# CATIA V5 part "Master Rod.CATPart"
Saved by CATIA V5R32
Part number: Master Rod
Bounding box of the stored display mesh (mm): x -55.99 to 55.99, y -51.999 to 267.322, z -35 to 35
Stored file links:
  D:\PROJECTS\Project 2022\CATIA V5 6R 2022\Resources\Part Files\c12_catia_v5_6r2022_prt\c12_catia_v5-6r2022 figr_12-26\Master Rod.CATPart
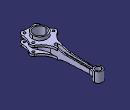
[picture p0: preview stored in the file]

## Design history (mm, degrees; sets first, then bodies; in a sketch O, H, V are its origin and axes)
Body1 (main body)
  Sketch1 on xy-plane, origin (0, 0, 0), H (1, 0, 0), V (0, 1, 0)
    arc A1 centre (0, 0) radius 31.5 from (-26.3425, 17.272) to (26.3425, 17.272) ccw
    arc A2 centre (0, 250) radius 17.5 from (14.7398, 240.5666) to (-14.7398, 240.5666) ccw
    point P1 (0, 250)
    line L1 (9, 220) -> (13, 60)
    point P2 (9, 220)
    point P3 (13, 60)
    arc A3 centre (94.6219, 62.0405) radius 81.6474 from (13, 60) to (26.3425, 17.272) ccw
    point P5 (26.3425, 17.272)
    arc A4 centre (45.4514, 220.9113) radius 36.4628 from (9, 220) to (14.7398, 240.5666) cw
    point P7 (14.7398, 240.5666)
    point P8 (-14.7398, 240.5666)
    point P9 (-9, 220)
    arc A5 centre (-45.4514, 220.9113) radius 36.4628 from (-9, 220) to (-14.7398, 240.5666) ccw
    point P11 (-13, 60)
    line L2 (-9, 220) -> (-13, 60)
    point P12 (-26.3425, 17.272)
    arc A6 centre (-94.6219, 62.0405) radius 81.6474 from (-13, 60) to (-26.3425, 17.272) cw
    radius A1 = 31.5
    radius A2 = 17.5
    distance P1 H = 250
    distance V P3 = 13
    distance P2 V = 9
    distance P1 P2 V = 30
    distance P3 P2 V = 160
    coincidence: P1 V
    tangency: A3 L1, A3 A1, A4 L1, A4 A2
    symmetry: P7 P8 V, P2 P9 V, A4 A5 V, P3 P11 V, L1 L2 V, P5 P12 V, A3 A6 V
  Pad1: profile Sketch1, direction (0, 0, 1), length 21, mirrored extent
  Sketch2 on face of Pad1, origin (0, 0, 21), H (1, 0, 0), V (0, 1, 0)
    point P1 (43, 16)
    point P2 (26, -39)
    arc A1 centre (43, 16) radius 13 from (53.3864, 8.1819) to (49.3111, 27.3653) ccw
    arc A2 centre (26, -39) radius 13 from (22.0235, -51.3769) to (38.9864, -38.4063) ccw
    reference projected line E1 (9, 220) -> (12.2872, 88.5122) from edge of Pad1
    arc A3 centre (84.2647, 90.3117) radius 72 from (49.3111, 27.3653) to (12.2872, 88.5122) cw
    point P5 (49.3111, 27.3653)
    point P6 (12.2872, 88.5122)
    arc A4 centre (110.9113, -35.118) radius 72 from (38.9864, -38.4063) to (53.3864, 8.1819) cw
    point P8 (38.9864, -38.4063)
    point P9 (53.3864, 8.1819)
    point P10 (-12.2872, 88.5122)
    point P11 (-49.3111, 27.3653)
    arc A5 centre (-84.2647, 90.3117) radius 72 from (-49.3111, 27.3653) to (-12.2872, 88.5122) ccw
    point P13 (-53.3864, 8.1819)
    arc A6 centre (-43, 16) radius 13 from (-53.3864, 8.1819) to (-49.3111, 27.3653) cw
    point P15 (-38.9864, -38.4063)
    arc A7 centre (-110.9113, -35.118) radius 72 from (-38.9864, -38.4063) to (-53.3864, 8.1819) ccw
    arc A8 centre (-26, -39) radius 13 from (-22.0235, -51.3769) to (-38.9864, -38.4063) cw
    line L1 (12.2872, 88.5122) -> (-12.2872, 88.5122)
    arc A9 centre (0, -119.9259) radius 72 from (-22.0235, -51.3769) to (22.0235, -51.3769) cw
    distance V P2 = 26
    distance P2 P1 H = 17
    distance P1 P2 V = 55
    distance P2 H = 39
    radius A1 = 13
    radius A2 = 13
    radius A3 = 72
    radius A4 = 72
    radius A9 = 72
    tangency: A3 E1, A3 A1, A4 A1, A4 A2, A9 A8, A9 A2
    symmetry: P6 P10 V, P5 P11 V, A3 A5 V, P9 P13 V, A1 A6 V, P8 P15 V, A4 A7 V, A2 A8 V
    horizontal: L1 H
  Pad2: profile Sketch2, direction (0, 0, -1), length 9
  Mirror1: of Pad2, Sketch2, about xy-plane
  Sketch3 on xy-plane, origin (0, 0, 0), H (1, 0, 0), V (0, 1, 0)
    circle A1 centre (0, 0) radius 31.5
    reference projected arc E1 centre (0, 0) radius 31.5 from (-26.3425, 17.272) to (26.3425, 17.272) ccw from edge of Pad2
    tangency: A1 E1
  Pad3: profile Sketch3, direction (0, 0, 1), length 35, mirrored extent
  Sketch4 on xy-plane, origin (0, 0, 0), H (1, 0, 0), V (0, 1, 0)
    circle A1 centre (0, 0) radius 26
    circle A2 centre (43, 16) radius 5
    circle A3 centre (26, -39) radius 5
    reference projected arc E1 centre (43, 16) radius 13 from (53.3864, 8.1819) to (49.3111, 27.3653) ccw from edge of Pad2
    reference projected arc E2 centre (26, -39) radius 13 from (22.0235, -51.3769) to (38.9864, -38.4063) ccw from edge of Pad2
    circle A4 centre (-26, -39) radius 5
    circle A5 centre (-43, 16) radius 5
    radius A1 = 26
    radius A3 = 5
    radius A2 = 5
    concentricity: A2 E1, A3 E2
    symmetry: A3 A4 V, A2 A5 V
  Pocket1: profile Sketch4, direction (0, 0, -1), length 35, mirrored extent
  Sketch5 on yz-plane, origin (0, 0, 0), H (0, 1, 0), V (0, 0, 1)
    line L1 (123.0834, 12) -> (250, 9)
    point P1 (123.0834, 12)
    point P2 (250, 9)
    arc A1 centre (124.9266, 89.9782) radius 78 from (88.5122, 21) to (123.0834, 12) ccw
    line L2 (88.5122, 21) -> (88.5122, 33.8539)
    line L3 (88.5122, 33.8539) -> (280.7471, 33.8539)
    line L4 (280.7471, 33.8539) -> (280.7471, 8.2732)
    point P8 (280.7471, 8.2732)
    line L5 (280.7471, 8.2732) -> (250, 9)
    distance P1 H = 12
    distance H P2 = 9
    distance V P2 = 250
    radius A1 = 78
    tangency: A1 L1, L5 A1
    vertical: L2 V, L4 V
    horizontal: L3 H
    coincidence: P8 L1
  Pocket2: profile Sketch5, direction (-1, 0, 0), length 35, mirrored extent
  Mirror2: of Pocket2, Sketch5, about xy-plane
  Sketch6 on xy-plane, origin (0, 0, 0), H (1, 0, 0), V (0, 1, 0)
    circle A1 centre (0, 250) radius 17.5
    point P1 (0, 250)
    reference projected arc E1 centre (0, 250) radius 17.5 from (17.5, 250) to (-17.5, 250) ccw from edge of Mirror2
    reference projected arc E2 centre (0, 250) radius 17.5 from (17.5, 250) to (-17.5, 250) ccw from edge of Mirror2
    coincidence: P1 V
    concentricity: E1 A1
    tangency: E2 A1
  Pad4: profile Sketch6, direction (0, 0, 1), length 21, mirrored extent
  Sketch7 on xy-plane, origin (0, 0, 0), H (1, 0, 0), V (0, 1, 0)
    circle A1 centre (0, 250) radius 12
    point P1 (0, 250)
    reference projected circle E1 centre (0, 250) radius 17.5 from edge of Pad4
    radius A1 = 12
    coincidence: P1 V
    concentricity: A1 E1
  Pocket3: profile Sketch7, direction (0, 0, -1), length 21, mirrored extent
  Sketch8 on xy-plane, origin (0, 0, 0), H (1, 0, 0), V (0, 1, 0)
    construction line L1 (0, 70) -> (0, 220)
    point P1 (0, 70)
    point P2 (0, 220)
    line L2 (-6, 70) -> (-6, 220)
    line L3 (6, 220) -> (6, 70)
    arc A1 centre (0, 220) radius 6 from (-6, 220) to (6, 220) cw
    arc A2 centre (0, 70) radius 6 from (6, 70) to (-6, 70) cw
    point P7 (0, 250)
    reference projected circle E1 centre (0, 250) radius 12 from edge of Pocket3
    length L1 = 150
    distance P7 P2 = 30
    radius A1 = 6
    coincidence: P1 V, P7 L1
    vertical: L1 V
    tangency: A1 L2, A2 L2, A1 L3, A2 L3
    parallelism: L1 L2
    concentricity: P7 E1
  Pocket4: profile Sketch8, direction (0, 0, 1), through (limit type 6), opposite side length -2.5
  Mirror3: of Pocket4, Sketch8, about xy-plane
